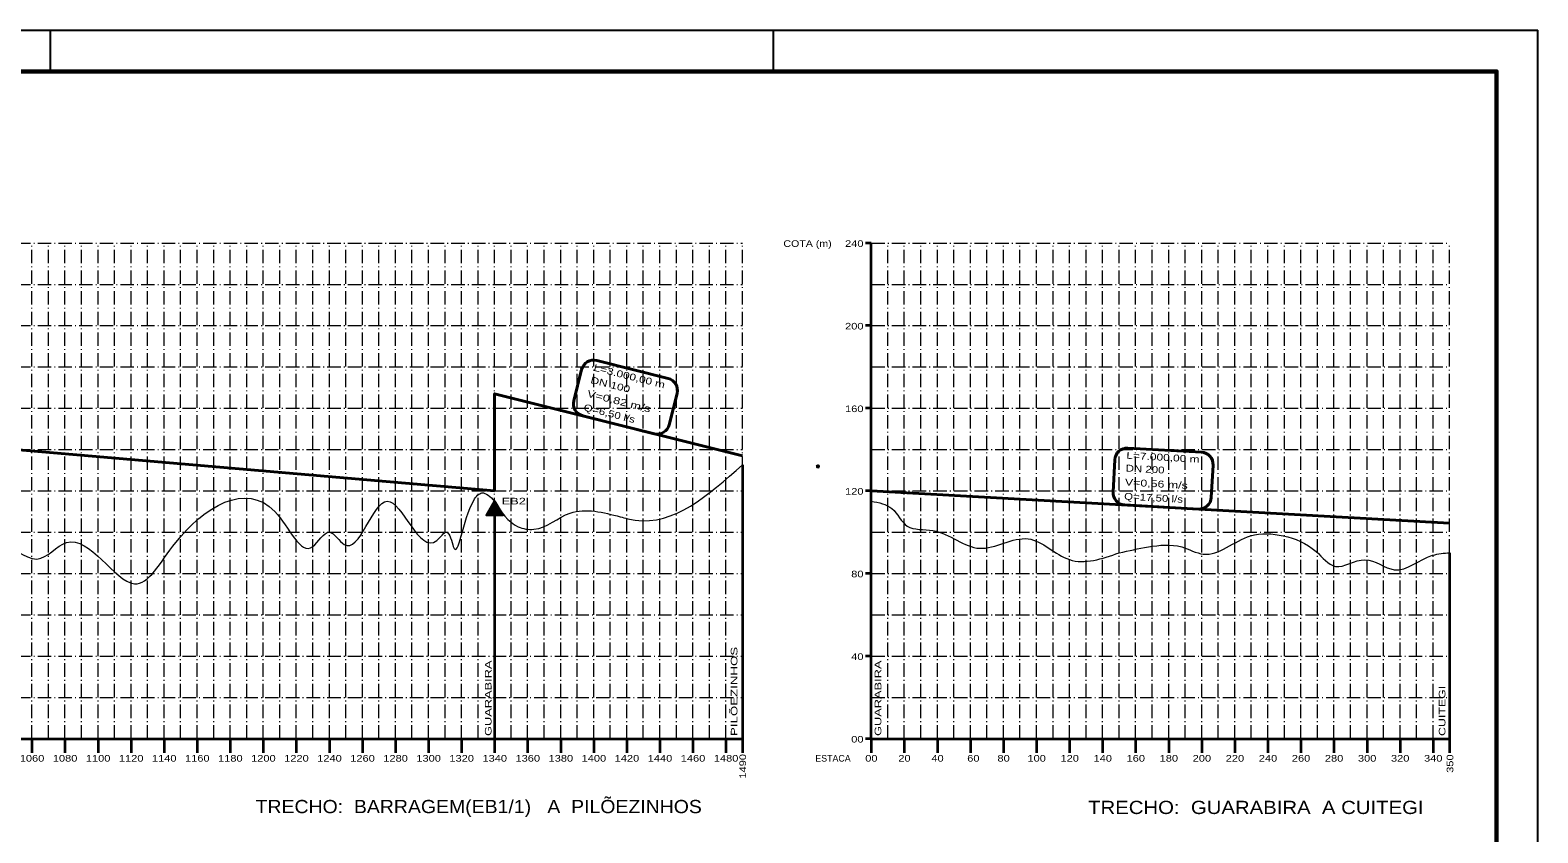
# Model space of a CAD drawing. Extents: x 0 to 1682, y 0 to 1188.
# Drawn here: x 952 to 1682, y 799 to 1188 of the extents above; entities that cross this region are included whole.
import ezdxf
from ezdxf.enums import TextEntityAlignment as Align

# ---------------------------------------------------------------- set-up
doc = ezdxf.new("R2010")
doc.units = 0
doc.header["$LTSCALE"] = 1.3
doc.header["$PDMODE"] = 32
doc.header["$PDSIZE"] = 0.65
doc.linetypes.add('DOT_DASHED', pattern=[7.7, 5, -1.2, 0.3, -1.2])
for name, color, linetype, lineweight in [('1', 7, 'DOT_DASHED', 13), ('55', 7, 'Continuous', 13), ('62', 7, 'Continuous', 13), ('63', 7, 'Continuous', 25), ('9', 7, 'Continuous', 40)]:
    doc.layers.add(name, color=color, linetype=linetype, lineweight=lineweight)
doc.layers.add('24', color=7, linetype='Continuous')

msp = doc.modelspace()

# ---------------------------------------------------------------- hatches: boundary and pattern name
at = {"layer": '62'}
msp.add_hatch(color=256, dxfattribs=at).paths.add_polyline_path([(1176.775, 959.796), (1180.721, 953.058), (1172.912, 953.009)])

# ---------------------------------------------------------------- linework, layer by layer
at = {"layer": '1'}
for p, q in [((104.775, 1084.796), (1296.775, 1084.796)), ((952.775, 844.796), (952.775, 1084.796)), ((960.775, 844.796), (960.775, 1084.796)), ((968.775, 844.796), (968.775, 1084.796)), ((976.775, 844.796), (976.775, 1084.796)), ((984.775, 844.796), (984.775, 1084.796)), ((992.775, 844.796), (992.775, 1084.796)), ((1000.775, 844.796), (1000.775, 1084.796)), ((1008.775, 844.796), (1008.775, 1084.796)), ((1016.775, 844.796), (1016.775, 1084.796)), ((1024.775, 844.796), (1024.775, 1084.796)), ((1032.775, 844.796), (1032.775, 1084.796)), ((1040.775, 844.796), (1040.775, 1084.796)), ((1048.775, 844.796), (1048.775, 1084.796)), ((1056.775, 844.796), (1056.775, 1084.796)), ((1064.775, 844.796), (1064.775, 1084.796)), ((1072.775, 844.796), (1072.775, 1084.796)), ((1080.775, 844.796), (1080.775, 1084.796)), ((1088.775, 844.796), (1088.775, 1084.796)), ((1096.775, 844.796), (1096.775, 1084.796)), ((1104.775, 844.796), (1104.775, 1084.796)), ((1112.775, 844.796), (1112.775, 1084.796)), ((1120.775, 844.796), (1120.775, 1084.796)), ((1128.775, 844.796), (1128.775, 1084.796)), ((1136.775, 844.796), (1136.775, 1084.796)), ((1144.775, 844.796), (1144.775, 1084.796)), ((1152.775, 844.796), (1152.775, 1084.796)), ((1160.775, 844.796), (1160.775, 1084.796)), ((1168.775, 844.796), (1168.775, 1084.796)), ((1176.775, 844.796), (1176.775, 1084.796)), ((1184.775, 844.796), (1184.775, 1084.796)), ((1192.775, 844.796), (1192.775, 1084.796)), ((1200.775, 844.796), (1200.775, 1084.796)), ((1208.775, 844.796), (1208.775, 1084.796)), ((1216.775, 844.796), (1216.775, 1084.796)), ((1224.775, 844.796), (1224.775, 1084.796)), ((1232.775, 844.796), (1232.775, 1084.796)), ((1240.775, 844.796), (1240.775, 1084.796)), ((1248.775, 844.796), (1248.775, 1084.796)), ((1256.775, 844.796), (1256.775, 1084.796)), ((1264.775, 844.796), (1264.775, 1084.796)), ((1272.775, 844.796), (1272.775, 1084.796)), ((1280.775, 844.796), (1280.775, 1084.796)), ((1288.775, 844.796), (1288.775, 1084.796)), ((1296.775, 844.796), (1296.775, 1084.796)), ((1359.125, 1084.796), (1639.125, 1084.796)), ((1367.125, 844.796), (1367.125, 1084.796)), ((1375.125, 844.796), (1375.125, 1084.796)), ((1383.125, 844.796), (1383.125, 1084.796)), ((1391.125, 844.796), (1391.125, 1084.796)), ((1399.125, 844.796), (1399.125, 1084.796)), ((1407.125, 844.796), (1407.125, 1084.796)), ((1415.125, 844.796), (1415.125, 1084.796)), ((1423.125, 844.796), (1423.125, 1084.796)), ((1431.125, 844.796), (1431.125, 1084.796)), ((1439.125, 844.796), (1439.125, 1084.796)), ((1447.125, 844.796), (1447.125, 1084.796)), ((1455.125, 844.796), (1455.125, 1084.796)), ((1463.125, 844.796), (1463.125, 1084.796)), ((1471.125, 844.796), (1471.125, 1084.796)), ((1479.125, 844.796), (1479.125, 1084.796)), ((1487.125, 844.796), (1487.125, 1084.796)), ((1495.125, 844.796), (1495.125, 1084.796)), ((1503.125, 844.796), (1503.125, 1084.796)), ((1511.125, 844.796), (1511.125, 1084.796)), ((1519.125, 844.796), (1519.125, 1084.796)), ((1527.125, 844.796), (1527.125, 1084.796)), ((1535.125, 844.796), (1535.125, 1084.796)), ((1543.125, 844.796), (1543.125, 1084.796)), ((1551.125, 844.796), (1551.125, 1084.796)), ((1559.125, 844.796), (1559.125, 1084.796)), ((1567.125, 844.796), (1567.125, 1084.796)), ((1575.125, 844.796), (1575.125, 1084.796)), ((1583.125, 844.796), (1583.125, 1084.796)), ((1591.125, 844.796), (1591.125, 1084.796)), ((1599.125, 844.796), (1599.125, 1084.796)), ((1607.125, 844.796), (1607.125, 1084.796)), ((1615.125, 844.796), (1615.125, 1084.796)), ((1623.125, 844.796), (1623.125, 1084.796)), ((1631.125, 844.796), (1631.125, 1084.796)), ((1639.125, 844.796), (1639.125, 1084.796)), ((104.775, 1064.796), (1296.775, 1064.796)), ((1359.125, 1064.796), (1639.125, 1064.796)), ((104.775, 1044.796), (1296.775, 1044.796)), ((1359.125, 1044.796), (1639.125, 1044.796)), ((104.775, 1024.796), (1296.775, 1024.796)), ((1359.125, 1024.796), (1639.125, 1024.796)), ((104.775, 1004.796), (1296.775, 1004.796)), ((1359.125, 1004.796), (1639.125, 1004.796)), ((104.775, 984.796), (1296.775, 984.796)), ((1359.125, 984.796), (1639.125, 984.796)), ((104.775, 964.796), (1296.775, 964.796)), ((1359.125, 964.796), (1639.125, 964.796)), ((104.775, 944.796), (1296.775, 944.796)), ((1359.125, 944.796), (1639.125, 944.796)), ((104.775, 924.796), (1296.775, 924.796)), ((1359.125, 924.796), (1639.125, 924.796)), ((104.775, 904.796), (1296.775, 904.796)), ((1359.125, 904.796), (1639.125, 904.796)), ((104.775, 884.796), (1296.775, 884.796)), ((1359.125, 884.796), (1639.125, 884.796)), ((104.775, 864.796), (1296.775, 864.796)), ((1359.125, 864.796), (1639.125, 864.796))]:
    msp.add_line(p, q, dxfattribs=at)
at = {"layer": '55', "lineweight": 35}
for p, q in [((1296.775, 977.352), (1296.775, 844.796)), ((1176.775, 959.796), (1176.775, 844.796)), ((1639.125, 934.796), (1639.125, 844.796))]:
    msp.add_line(p, q, dxfattribs=at)
at = {"layer": '55'}
for points in [[(1176.775, 959.796), (1188.231, 947.409), (1195.801, 946.199), (1213.363, 954.062), (1237.586, 952.248), (1244.82, 950.644), (1296.775, 977.352)], [(104.775, 889.796), (114.375, 884.796), (116.375, 879.796), (118.375, 884.796), (119.975, 894.796), (121.575, 884.796), (123.175, 894.796), (132.775, 917.796), (136.775, 904.796), (139.175, 889.796), (149.575, 922.796), (165.575, 914.796), (186.375, 873.796), (227.175, 913.796), (235.175, 904.796), (242.375, 914.796), (258.375, 918.796), (266.375, 922.796), (287.975, 922.796), (300.775, 914.796), (308.775, 894.796), (310.375, 899.796), (311.975, 894.796), (328.775, 879.796), (343.175, 904.796), (367.975, 926.796), (388.775, 924.796), (402.375, 927.796), (434.375, 931.796), (442.375, 925.796), (475.175, 954.796), (488.775, 939.796), (492.775, 937.796), (524.775, 949.796), (534.375, 944.796), (536.775, 941.796), (551.175, 956.796), (559.175, 958.796), (579.175, 944.796), (588.775, 954.796), (595.175, 944.796), (607.175, 934.796), (615.975, 947.796), (631.975, 929.796), (651.975, 894.796), (653.575, 889.796), (659.975, 909.796), (663.175, 904.796), (669.575, 898.796), (687.975, 886.796), (697.575, 888.796), (703.975, 886.796), (707.975, 894.796), (711.975, 890.796), (728.775, 894.796), (731.975, 896.796), (734.375, 894.796), (753.575, 910.796), (767.975, 889.796), (787.975, 914.796), (806.375, 922.796), (826.375, 898.796), (830.375, 904.796), (837.575, 897.796), (841.575, 899.796), (846.375, 904.796), (850.375, 889.796), (854.375, 902.796), (863.975, 899.796), (878.375, 924.796), (911.175, 941.796), (923.975, 927.796), (936.775, 937.796), (955.175, 931.796), (969.575, 939.796), (1002.375, 919.796), (1022.375, 939.796), (1070.375, 954.796), (1088.775, 937.796), (1096.775, 944.796), (1103.975, 938.796), (1124.775, 959.796), (1148.775, 940.796), (1153.575, 944.796), (1156.775, 937.796), (1166.644, 960.143), (1170.611, 963.809), (1176.775, 959.796)], [(1359.125, 959.796), (1369.15, 956.216), (1376.553, 947.787), (1388.988, 945.568), (1411.639, 936.991), (1435.03, 941.576), (1455.017, 931.52), (1479.125, 934.796)], [(1479.125, 934.796), (1493.273, 937.651), (1509.399, 937.651), (1519.88, 934.155), (1542.724, 943.029), (1558.58, 943.029), (1574.437, 935.5), (1583.843, 928.24), (1598.087, 931.467), (1612.331, 926.627), (1630.875, 933.618), (1639.125, 934.796)]]:
    msp.add_spline(points, degree=3, dxfattribs=at)
at = {"layer": '62', "lineweight": 35}
for p, q in [((1359.125, 1084.796), (1356.394, 1084.796)), ((1358.956, 1084.796), (1359.125, 1084.796)), ((1359.125, 844.796), (1359.125, 1084.796)), ((1358.956, 1074.796), (1359.125, 1074.796)), ((1358.956, 1064.796), (1359.125, 1064.796)), ((1358.956, 1054.796), (1359.125, 1054.796)), ((1359.125, 1044.796), (1356.394, 1044.796)), ((1358.956, 1044.796), (1359.125, 1044.796)), ((1358.956, 1034.796), (1359.125, 1034.796)), ((1358.956, 1024.796), (1359.125, 1024.796)), ((1358.956, 1014.796), (1359.125, 1014.796)), ((1359.125, 1004.796), (1356.394, 1004.796)), ((1358.956, 1004.796), (1359.125, 1004.796)), ((1358.956, 994.796), (1359.125, 994.796)), ((1358.956, 984.796), (1359.125, 984.796)), ((1358.956, 974.796), (1359.125, 974.796)), ((1359.125, 964.796), (1356.394, 964.796)), ((1358.956, 964.796), (1359.125, 964.796)), ((1358.956, 954.796), (1359.125, 954.796)), ((1358.956, 944.796), (1359.125, 944.796)), ((1358.956, 934.796), (1359.125, 934.796)), ((1359.125, 924.796), (1356.394, 924.796)), ((1358.956, 924.796), (1359.125, 924.796)), ((1358.956, 914.796), (1359.125, 914.796)), ((1358.956, 904.796), (1359.125, 904.796)), ((1358.956, 894.796), (1359.125, 894.796)), ((1359.125, 884.796), (1356.394, 884.796)), ((1358.956, 884.796), (1359.125, 884.796)), ((1358.956, 874.796), (1359.125, 874.796)), ((1358.956, 864.796), (1359.125, 864.796)), ((1358.956, 854.796), (1359.125, 854.796)), ((952.775, 844.796), (952.775, 837.968)), ((968.775, 844.796), (968.775, 837.968)), ((984.775, 844.796), (984.775, 837.968)), ((1000.775, 844.796), (1000.775, 837.968)), ((1016.775, 844.796), (1016.775, 837.968)), ((1032.775, 844.796), (1032.775, 837.968)), ((1048.775, 844.796), (1048.775, 837.968)), ((1064.775, 844.796), (1064.775, 837.968)), ((1080.775, 844.796), (1080.775, 837.968)), ((1096.775, 844.796), (1096.775, 837.968)), ((1112.775, 844.796), (1112.775, 837.968)), ((1128.775, 844.796), (1128.775, 837.968)), ((1144.775, 844.796), (1144.775, 837.968)), ((1160.775, 844.796), (1160.775, 837.968)), ((1176.775, 844.796), (1176.775, 837.968)), ((1176.775, 844.796), (1296.775, 844.796)), ((1192.775, 844.796), (1192.775, 837.968)), ((1208.775, 844.796), (1208.775, 837.968)), ((1224.775, 844.796), (1224.775, 837.968)), ((1240.775, 844.796), (1240.775, 837.968)), ((1256.775, 844.796), (1256.775, 837.968)), ((1272.775, 844.796), (1272.775, 837.968)), ((1288.775, 844.796), (1288.775, 837.968)), ((1296.775, 844.796), (1296.775, 837.968)), ((1359.125, 844.796), (1356.394, 844.796)), ((1359.125, 844.796), (1359.125, 837.968)), ((1359.125, 844.796), (1639.125, 844.796)), ((1375.125, 844.796), (1375.125, 837.968)), ((1391.125, 844.796), (1391.125, 837.968)), ((1407.125, 844.796), (1407.125, 837.968)), ((1423.125, 844.796), (1423.125, 837.968)), ((1439.125, 844.796), (1439.125, 837.968)), ((1455.125, 844.796), (1455.125, 837.968)), ((1471.125, 844.796), (1471.125, 837.968)), ((1487.125, 844.796), (1487.125, 837.968)), ((1503.125, 844.796), (1503.125, 837.968)), ((1519.125, 844.796), (1519.125, 837.968)), ((1535.125, 844.796), (1535.125, 837.968)), ((1551.125, 844.796), (1551.125, 837.968)), ((1567.125, 844.796), (1567.125, 837.968)), ((1583.125, 844.796), (1583.125, 837.968)), ((1599.125, 844.796), (1599.125, 837.968)), ((1615.125, 844.796), (1615.125, 837.968)), ((1631.125, 844.796), (1631.125, 837.968)), ((1639.125, 844.796), (1639.125, 837.968))]:
    msp.add_line(p, q, dxfattribs=at)
at = {"layer": '62'}
for p, q in [((1358.956, 1082.796), (1359.125, 1082.796)), ((1358.956, 1080.796), (1359.125, 1080.796)), ((1358.956, 1078.796), (1359.125, 1078.796)), ((1358.956, 1076.796), (1359.125, 1076.796)), ((1358.956, 1072.796), (1359.125, 1072.796)), ((1358.956, 1070.796), (1359.125, 1070.796)), ((1358.956, 1068.796), (1359.125, 1068.796)), ((1358.956, 1066.796), (1359.125, 1066.796)), ((1358.956, 1062.796), (1359.125, 1062.796)), ((1358.956, 1060.796), (1359.125, 1060.796)), ((1358.956, 1058.796), (1359.125, 1058.796)), ((1358.956, 1056.796), (1359.125, 1056.796)), ((1358.956, 1052.796), (1359.125, 1052.796)), ((1358.956, 1050.796), (1359.125, 1050.796)), ((1358.956, 1048.796), (1359.125, 1048.796)), ((1358.956, 1046.796), (1359.125, 1046.796)), ((1358.956, 1042.796), (1359.125, 1042.796)), ((1358.956, 1040.796), (1359.125, 1040.796)), ((1358.956, 1038.796), (1359.125, 1038.796)), ((1358.956, 1036.796), (1359.125, 1036.796)), ((1358.956, 1032.796), (1359.125, 1032.796)), ((1358.956, 1030.796), (1359.125, 1030.796)), ((1358.956, 1028.796), (1359.125, 1028.796)), ((1358.956, 1026.796), (1359.125, 1026.796)), ((1358.956, 1022.796), (1359.125, 1022.796)), ((1358.956, 1020.796), (1359.125, 1020.796)), ((1358.956, 1018.796), (1359.125, 1018.796)), ((1358.956, 1016.796), (1359.125, 1016.796)), ((1358.956, 1012.796), (1359.125, 1012.796)), ((1358.956, 1010.796), (1359.125, 1010.796)), ((1358.956, 1008.796), (1359.125, 1008.796)), ((1358.956, 1006.796), (1359.125, 1006.796)), ((1358.956, 1002.796), (1359.125, 1002.796)), ((1358.956, 1000.796), (1359.125, 1000.796)), ((1358.956, 998.796), (1359.125, 998.796)), ((1358.956, 996.796), (1359.125, 996.796)), ((1358.956, 992.796), (1359.125, 992.796)), ((1358.956, 990.796), (1359.125, 990.796)), ((1358.956, 988.796), (1359.125, 988.796)), ((1358.956, 986.796), (1359.125, 986.796)), ((1358.956, 982.796), (1359.125, 982.796)), ((1358.956, 980.796), (1359.125, 980.796)), ((1358.956, 978.796), (1359.125, 978.796)), ((1358.956, 976.796), (1359.125, 976.796)), ((1358.956, 972.796), (1359.125, 972.796)), ((1358.956, 970.796), (1359.125, 970.796)), ((1358.956, 968.796), (1359.125, 968.796)), ((1358.956, 966.796), (1359.125, 966.796)), ((1358.956, 962.796), (1359.125, 962.796)), ((1358.956, 960.796), (1359.125, 960.796)), ((1358.956, 958.796), (1359.125, 958.796)), ((1358.956, 956.796), (1359.125, 956.796)), ((1358.956, 952.796), (1359.125, 952.796)), ((1358.956, 950.796), (1359.125, 950.796)), ((1358.956, 948.796), (1359.125, 948.796)), ((1358.956, 946.796), (1359.125, 946.796)), ((1358.956, 942.796), (1359.125, 942.796)), ((1358.956, 940.796), (1359.125, 940.796)), ((1358.956, 938.796), (1359.125, 938.796)), ((1358.956, 936.796), (1359.125, 936.796)), ((1358.956, 932.796), (1359.125, 932.796)), ((1358.956, 930.796), (1359.125, 930.796)), ((1358.956, 928.796), (1359.125, 928.796)), ((1358.956, 926.796), (1359.125, 926.796)), ((1358.956, 922.796), (1359.125, 922.796)), ((1358.956, 920.796), (1359.125, 920.796)), ((1358.956, 918.796), (1359.125, 918.796)), ((1358.956, 916.796), (1359.125, 916.796)), ((1358.956, 912.796), (1359.125, 912.796)), ((1358.956, 910.796), (1359.125, 910.796)), ((1358.956, 908.796), (1359.125, 908.796)), ((1358.956, 906.796), (1359.125, 906.796)), ((1358.956, 902.796), (1359.125, 902.796)), ((1358.956, 900.796), (1359.125, 900.796)), ((1358.956, 898.796), (1359.125, 898.796)), ((1358.956, 896.796), (1359.125, 896.796)), ((1358.956, 892.796), (1359.125, 892.796)), ((1358.956, 890.796), (1359.125, 890.796)), ((1358.956, 888.796), (1359.125, 888.796)), ((1358.956, 886.796), (1359.125, 886.796)), ((1358.956, 882.796), (1359.125, 882.796)), ((1358.956, 880.796), (1359.125, 880.796)), ((1358.956, 878.796), (1359.125, 878.796)), ((1358.956, 876.796), (1359.125, 876.796)), ((1358.956, 872.796), (1359.125, 872.796)), ((1358.956, 870.796), (1359.125, 870.796)), ((1358.956, 868.796), (1359.125, 868.796)), ((1358.956, 866.796), (1359.125, 866.796)), ((1358.956, 862.796), (1359.125, 862.796)), ((1358.956, 860.796), (1359.125, 860.796)), ((1358.956, 858.796), (1359.125, 858.796)), ((1358.956, 856.796), (1359.125, 856.796)), ((1358.956, 852.796), (1359.125, 852.796)), ((1358.956, 850.796), (1359.125, 850.796)), ((1358.956, 848.796), (1359.125, 848.796)), ((1358.956, 846.796), (1359.125, 846.796))]:
    msp.add_line(p, q, dxfattribs=at)
at = {"layer": '62', "lineweight": 35}
msp.add_lwpolyline([(1176.775, 959.796), (1180.721, 953.058), (1172.912, 953.009)], close=True, dxfattribs=at)
msp.add_lwpolyline([(104.775, 844.796), (384.775, 844.796), (1176.775, 844.796)], dxfattribs=at)
at = {"layer": '63'}
for p, q in [((-0.168, 1187.881), (1681.832, 1187.881)), ((961.832, 1167.881), (961.832, 1187.881)), ((1311.832, 1167.881), (1311.832, 1187.881)), ((1681.832, -0.119), (1681.832, 1187.881)), ((1681.832, -0.119), (1681.832, 1187.881))]:
    msp.add_line(p, q, dxfattribs=at)
msp.add_lwpolyline([(-0.168, -0.119), (1681.832, -0.119), (1681.832, 1187.881)], dxfattribs=at)
at = {"layer": '63', "lineweight": 60}
msp.add_lwpolyline([(49.832, 1167.881), (1661.832, 1167.881), (1661.832, 19.881), (1311.832, 19.881)], dxfattribs=at)
at = {"layer": '63'}
msp.add_point((1661.832, 1167.881), dxfattribs=at)
at = {"layer": '9'}
for p, q in [((1218.918, 1023.562), (1215.128, 1008.419)), ((1226.196, 1027.926), (1260.763, 1019.273)), ((1265.127, 1011.995), (1261.336, 996.852)), ((1219.491, 1001.142), (1254.058, 992.489)), ((1483.363, 985.531), (1518.942, 983.55)), ((1477.039, 979.874), (1476.171, 964.288)), ((1524.599, 977.226), (1523.732, 961.639)), ((1359.125, 964.796), (1639.125, 949.205)), ((1481.828, 957.963), (1517.407, 955.982))]:
    msp.add_line(p, q, dxfattribs=at)
for points in [[(104.775, 1070.086), (148.775, 1062.526), (672.775, 1008.226), (1176.775, 964.796)], [(1176.775, 964.796), (1176.775, 1011.834), (1296.775, 981.796)]]:
    msp.add_lwpolyline(points, dxfattribs=at)
for centre, start, end in [((1224.739, 1022.105), 75.94643, 165.94643), ((1259.306, 1013.452), 345.94643, 75.94643), ((1220.948, 1006.962), 165.94643, 255.94643), ((1255.515, 998.309), 255.94643, 345.94643), ((1483.03, 979.54), 86.81296, 176.81296), ((1518.609, 977.559), 356.81296, 86.81296), ((1482.162, 963.954), 176.81296, 266.81296), ((1517.741, 961.973), 266.81296, 356.81296)]:
    msp.add_arc(centre, 6, start, end, dxfattribs=at)
msp.add_point((1333.302, 976.67), dxfattribs=at)

# ---------------------------------------------------------------- texts
at = {"layer": '24'}
for s, width, p in [('COTA (m)', 1.2, (1339.975, 1082.94)), ('240', 1.25, (1355.371, 1082.94)), ('200', 1.25, (1355.371, 1042.94)), ('160', 1.25, (1355.371, 1002.94)), ('120', 1.25, (1355.371, 962.94)), ('80', 1.25, (1355.371, 922.94)), ('40', 1.25, (1355.371, 882.94)), ('00', 1.25, (1355.371, 842.94))]:
    msp.add_text(s, height=3.2, dxfattribs=dict(at, width=width)).set_placement(p, align=Align.RIGHT)
at = {"layer": '24', "width": 1.45}
msp.add_text('EB2', height=3.2, dxfattribs=at).set_placement((1180.177, 958.238))
at = {"layer": '24'}
for s, width, p in [('PILÕEZINHOS', 1.5, (1294.335, 846.113)), ('GUARABIRA', 1.45, (1175.282, 846.113)), ('GUARABIRA', 1.45, (1363.992, 846.113)), ('CUITEGI', 1.4, (1637.091, 846.113))]:
    msp.add_text(s, height=3.2, rotation=90, dxfattribs=dict(at, width=width)).set_placement(p)
for s, height, width, p in [('1060', 3.2, 1.25, (952.84, 833.708)), ('1080', 3.2, 1.25, (968.84, 833.708)), ('1100', 3.2, 1.25, (984.84, 833.708)), ('1120', 3.2, 1.25, (1000.84, 833.708)), ('1140', 3.2, 1.25, (1016.84, 833.708)), ('1160', 3.2, 1.25, (1032.84, 833.708)), ('1180', 3.2, 1.25, (1048.84, 833.708)), ('1200', 3.2, 1.25, (1064.84, 833.708)), ('1220', 3.2, 1.25, (1080.84, 833.708)), ('1240', 3.2, 1.25, (1096.84, 833.708)), ('1260', 3.2, 1.25, (1112.84, 833.708)), ('1280', 3.2, 1.25, (1128.84, 833.708)), ('1300', 3.2, 1.25, (1144.84, 833.708)), ('1320', 3.2, 1.25, (1160.84, 833.708)), ('1340', 3.2, 1.25, (1176.84, 833.708)), ('1360', 3.2, 1.25, (1192.84, 833.708)), ('1380', 3.2, 1.25, (1208.84, 833.708)), ('1400', 3.2, 1.25, (1224.84, 833.708)), ('1420', 3.2, 1.25, (1240.84, 833.708)), ('1440', 3.2, 1.25, (1256.84, 833.708)), ('1460', 3.2, 1.25, (1272.84, 833.708)), ('1480', 3.2, 1.25, (1288.84, 833.708)), ('00', 3.2, 1.25, (1359.19, 833.708)), ('20', 3.2, 1.25, (1375.19, 833.708)), ('40', 3.2, 1.25, (1391.19, 833.708)), ('60', 3.2, 1.25, (1408.562, 833.708)), ('80', 3.2, 1.25, (1423.19, 833.708)), ('100', 3.2, 1.25, (1439.19, 833.708)), ('120', 3.2, 1.25, (1455.19, 833.708)), ('140', 3.2, 1.25, (1471.19, 833.708)), ('160', 3.2, 1.25, (1487.19, 833.708)), ('180', 3.2, 1.25, (1503.19, 833.708)), ('200', 3.2, 1.25, (1519.19, 833.708)), ('220', 3.2, 1.25, (1535.19, 833.708)), ('240', 3.2, 1.25, (1551.19, 833.708)), ('260', 3.2, 1.25, (1567.19, 833.708)), ('280', 3.2, 1.25, (1583.19, 833.708)), ('300', 3.2, 1.25, (1599.19, 833.708)), ('320', 3.2, 1.25, (1615.19, 833.708)), ('340', 3.2, 1.25, (1631.19, 833.708)), ('TRECHO:  BARRAGEM(EB1/1)   A  PILÕEZINHOS', 6.4, 1.1, (1169.092, 808.754)), ('TRECHO:  GUARABIRA  A CUITEGI', 6.4, 1.15, (1545.312, 808.335))]:
    msp.add_text(s, height=height, dxfattribs=dict(at, width=width)).set_placement(p, align=Align.CENTER)
at = {"layer": '24', "width": 1.25}
for s, p in [('1490', (1298.507, 831.431)), ('350', (1640.888, 832.738))]:
    msp.add_text(s, height=3.2, rotation=90, dxfattribs=at).set_placement(p, align=Align.CENTER)
at = {"layer": '24'}
msp.add_text('ESTACA', height=3.2, dxfattribs=at).set_placement((1340.6, 833.708), align=Align.CENTER)
at = {"layer": '9'}
for s, rotation, width, p in [('L=3.000,00 m', 345.946, 1.3, (1224.438, 1023.027)), ('DN 100', 345.946, 1.3, (1222.938, 1017.032)), ('V=0,82 m/s', 345.946, 1.4, (1221.281, 1010.413)), ('Q=6,50 l/s', 345.946, 1.25, (1219.624, 1003.794)), ('L=7.000,00 m', 356.813, 1.3, (1482.561, 980.389)), ('DN 200', 356.813, 1.25, (1482.217, 974.219)), ('Q=17,50 l/s', 356.813, 1.25, (1481.459, 960.593)), ('V=0,56 m/s', 356.813, 1.35, (1481.838, 967.406))]:
    msp.add_text(s, height=3.319, rotation=rotation, dxfattribs=dict(at, width=width)).set_placement(p)

doc.saveas('drawing.dxf')
